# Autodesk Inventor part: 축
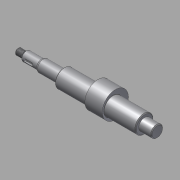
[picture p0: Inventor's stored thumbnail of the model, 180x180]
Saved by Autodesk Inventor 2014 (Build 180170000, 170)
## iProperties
Created: 2015-12
Part Number: 축
Document SubType Name: Modeling
Designer: mdu
Density: 7.86 g/cm^3
Material: 강철, 연강
Appearance: 강철
Mass: 489.709 g
Surface Area: 127.382 cm^2
Volume: 62.304 cm^3
Author: mdu
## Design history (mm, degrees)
sketch "스케치1"
  geometry: L1 (62, 100.9)-(62, 67.1) reference; L2 (51, 101.2)-(51, 84) reference; L3 (-51, 84)-(-51, 101.2) reference; L4 (-62, 67.1)-(-62, 100.9) reference; L5 (-51.6, 91.5)-(-61.4, 91.5) reference; L6 (51.6, 91.5)-(61.4, 91.5) reference; L7 (67, 84)-(-109, 84); L8 (-77, 64.201)-(-77, 103.799) reference; L9 (67, 84)-(67, 91.5); L10 (67, 91.5)-(51, 91.5); L11 (51, 91.5)-(51, 95.5); L12 (51, 95.5)-(-51, 95.5); L13 (-51, 95.5)-(-51, 91.5); L14 (-51, 91.5)-(-79, 91.5); L15 (-79, 91.5)-(-79, 90); L16 (-79, 90)-(-99, 90); L17 (-99, 90)-(-99, 87); L18 (-100.5, 88)-(-109, 88); L19 (-109, 88)-(-109, 84); L20 (-99, 87)-(-100.5, 87); L21 (-100.5, 87)-(-100.5, 88); 2 further points
  constraints: 32 end point, 7 parallel, 6 point on line, 5 perpendicular, 2 collinear, 2 horizontal, 1 midpoint, 4 other
  dimensions: "d0" = 5 distance from line of L7.start L1; "d2" = 2 distance between parallel lines of L15 L8; "d3" = 23 diameter of L12 L7; "d4" = 12 diameter of L16 L7; "d5" = 1.5 distance of L17.end L20.end; "d6" = 6 diameter of L20 L7; "d7" = 20 distance of L15.end L16.end; "d8" = 10 distance between parallel lines of L17 L19; "d9" = 8 diameter of L18 L7
revolve "회전1" sketch "스케치1" stored, may be unused: angle "d10" = 90 deg
sketch "스케치2"
  geometry: C1 r 11.5 at (84, 0) reference; C2 r 11.5 at (84, 0) reference; C3 r 16.5 at (87, 0); 1 further point
  constraints: 1 centre point, 1 horizontal alignment
  dimensions: "d11" = 33 diameter of C3; "d12" = 3 distance of C3.centre C1.centre
extrude "돌출1" join sketch "스케치2" stored distance "d13" = 22; taper "d14" = 0 deg
chamfer "모따기1" distance "d15" = 1; stored, may be unused: second distance "d16" = 2, angle "d17" = 45 deg
feature "스레드1" dims "d18" = 10, "d19" = 0
node "작업 평면1"
sketch "스케치3"
  geometry: L1 (-5, -2)-(3, -2); L2 (3, 2)-(-5, 2); L3 (-10, -5)-(-10, 5) reference; A1 r 2 centre (3, 0) between (3, -2) and (3, 2); A2 r 2 centre (-5, 0) between (-5, 2) and (-5, -2); 2 further points
  constraints: 4 end point, 4 point on circle, 4 tangent, 2 centre point, 1 horizontal, 1 horizontal alignment, 1 midpoint, 1 parallel
  dimensions: "d20" = 4 distance between parallel lines of L1 L2; "d21" = 12 dimension on A1 A2; "d22" = 3 distance edge to line of A2 L3
extrude "돌출2" cut sketch "스케치3" distance "d23" = 2.5; taper "d24" = 0 deg
fillet "모깎기1" dims "d25" = 0.3
fillet "모깎기2" dims "d26" = 3
node "솔리드1"
node "참조1"
node "참조2"
node "참조3"
node "참조4"
node "참조5"
node "투영된 루프1"
